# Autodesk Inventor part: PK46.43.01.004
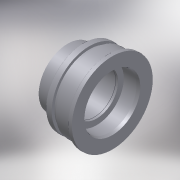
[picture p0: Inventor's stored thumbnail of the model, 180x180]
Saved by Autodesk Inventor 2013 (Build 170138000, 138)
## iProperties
Shininess: 64.0
Length Units: 11269
Angle Units: 11279
Time Units: 11290
Mass Units: 11283
Length Display Precision: 3
Angle Display Precision: 2
Compacted: True
Part Number: PK46.43.01.004
Document SubType Name: Modeling
Created: 2004-11
Material: Сталь низкоуглеродистая
Designer: ELarisa
Manufacturer: Standard
Standards Organization: Custom
Density: 7.86 g/cm^3
Density: 0.0
Volumn: 0.0
Area: 0.0
PropertySet Name: Model Information
Control State: 0
Master: False
Checked Out: False
Checked Out Date: 2008-10-09
Last Check In Date: 2008-10-09
Author: ELarisa
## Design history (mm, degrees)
revolve "Вращение1" stored, may be unused: angle "d17" = 90 deg
chamfer "Фаска1" distance "d18" = 1; stored, may be unused: second distance "d19" = 2, angle "d20" = 45 deg
body "Solid1"
sketch "Эскиз1"
  geometry: L1 (0, 0)-(0, 48); L2 (0, 48)-(26, 48); L3 (26, 48)-(26, 62.5); L4 (67, 62.5)-(67, 67); L5 (67, 67)-(74, 67); L6 (74, 67)-(74, 0); L7 (74, 0)-(0, 0); L8 (4, 35.5)-(4, 37.5); L9 (4, 37.5)-(44, 37.5); L10 (44, 37.5)-(44, 35.5); L11 (44, 35.5)-(48, 35.5); L12 (48, 35.5)-(48, 45); L13 (48, 45)-(69, 45); L14 (69, 45)-(74, 46.34); L15 (36, 62.5)-(36, 57.9); L16 (36, 57.9)-(43, 57.9); L17 (43, 57.9)-(43, 62.5); L18 (26, 62.5)-(36, 62.5); L19 (43, 62.5)-(67, 62.5); L20 (4, 35.5)-(0, 35.5)
  constraints: 40 end point, 9 parallel, 6 perpendicular, 2 collinear, 2 point on line, 1 vertical, 1 other
  dimensions: "d0" = 74 distance of L6.end L1.start; "d1" = 7 distance of L4.end L5.end; "d2" = 43 distance between parallel lines of L1 L17; "d3" = 7 distance of L15.end L16.end; "d4" = 26 distance of L1.end L2.end; "d5" = 5 horizontal distance of L13.end L14.end; "d6" = 26 distance between parallel lines of L6 L12; "d8" = 40 distance of L8.end L9.end; "d9" = 67 distance between parallel lines of L5 L7; "d10" = 62.5 distance between parallel lines of L19 L7; "d11" = 57.9 distance between parallel lines of L7 L16; "d12" = 48 distance between parallel lines of L7 L2; "d13" = 45 distance between parallel lines of L7 L13; "d14" = 35.5 distance between parallel lines of L7 L11; "d15" = 37.5 distance between parallel lines of L7 L9; "d16" = 4 distance of L8.start L20.end; "d21" = 15 deg angle of L13 L14
